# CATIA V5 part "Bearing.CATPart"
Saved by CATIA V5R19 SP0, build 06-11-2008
Part number: Bearing
Bounding box of the stored display mesh (mm): x -10 to 10, y -17.5 to 17.5, z -17.322 to 17.322
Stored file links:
  D:\Shriniwas\v5_r19\c16_CAT_v5r19\c16_Part\Cam_Follower_msm_trial\Bearing.CATPart
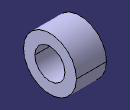
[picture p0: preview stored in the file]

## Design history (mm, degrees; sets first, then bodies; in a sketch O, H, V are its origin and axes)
Body1 (main body)
  Sketch1 on yz-plane, origin (0, 0, 0), H (0, 1, 0), V (0, 0, 1)
    circle A1 centre (0, 0) radius 10
    circle A2 centre (0, 0) radius 17.5
    radius A1 = 10
    radius A2 = 17.5
  Pad1: profile Sketch1, direction (1, 0, 0), length 10, mirrored extent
